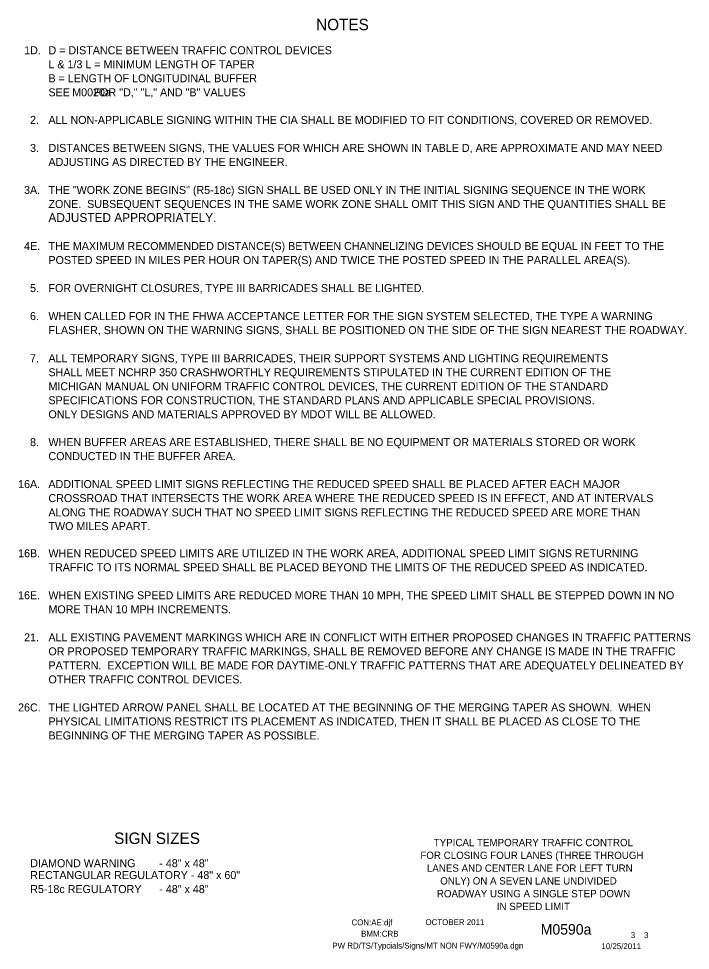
# Model space of a CAD drawing. Extents: x 16730 to 19504, y 5662 to 6979.
# Drawn here: x 18799 to 19504, y 5932 to 6909 of the extents above; entities that cross this region are included whole.
import ezdxf

# ---------------------------------------------------------------- set-up
doc = ezdxf.new("R2010")
doc.units = 0
for name, color, linetype in [('BORDER', 7, 'Continuous'), ('BORDER_SIGNAL_WO', 7, 'Continuous'), ('TYPICAL_TEXT_DIMEN_PR', 7, 'Continuous')]:
    doc.layers.add(name, color=color, linetype=linetype)

msp = doc.modelspace()

# ---------------------------------------------------------------- linework, layer by layer
at = {"layer": 'BORDER'}
msp.add_line((18938.25, 6055), (18938.25, 6055), dxfattribs=at)

# ---------------------------------------------------------------- texts
for s, p in [('TYPICAL TEMPORARY TRAFFIC CONTROL', (19234.94, 6041.12)), ('FOR CLOSING FOUR LANES (THREE THROUGH', (19220.94, 6027.72)), ('LANES AND CENTER LANE FOR LEFT TURN', (19227.78, 6014.31)), ('ONLY) ON A SEVEN LANE UNDIVIDED', (19241.76, 6000.91)), ('ROADWAY USING A SINGLE STEP DOWN', (19238.28, 5987.51)), ('IN SPEED LIMIT', (19301.15, 5974.1))]:
    msp.add_text(s, height=7.6471, dxfattribs=at).set_placement(p)
at = {"layer": 'BORDER_SIGNAL_WO'}
for s, height, p in [('CON:AE:djf', 6.2, (19148.69, 5958.06)), ('    OCTOBER 2011    ', 6.2, (19217.08, 5958.34)), ('BMM:CRB   ', 6.2, (19158.81, 5946.17)), ('    M0590a   ', 11, (19330.86, 5948.38)), (' 3    3 ', 6.2, (19439.45, 5944.7)), ('PW RD/TS/Typcials/Signs/MT NON FWY/M0590a.dgn    ', 6.2, (19128.55, 5933.71)), ('10/25/2011    ', 6.2, (19410.93, 5933.13))]:
    msp.add_text(s, height=height, dxfattribs=at).set_placement(p)
at = {"layer": 'TYPICAL_TEXT_DIMEN_PR'}
for s, height, p in [('NOTES', 12, (19111.55, 6897)), ('1D.', 8.4, (18805.19, 6871.81)), ('D = DISTANCE BETWEEN TRAFFIC CONTROL DEVICES', 8.4, (18830.7, 6871.81)), ('L & 1/3 L = MINIMUM LENGTH OF TAPER', 8.4, (18830.7, 6857.11)), ('B = LENGTH OF LONGITUDINAL BUFFER', 8.4, (18830.7, 6842.41)), ('SEE        FOR "D," "L," AND "B" VALUES', 8.4, (18830.7, 6827.71)), ('M0020a', 8.4, (18855.62, 6827.71)), ('2.', 8.4, (18811.39, 6798.75)), ('ALL NON-APPLICABLE SIGNING WITHIN THE CIA SHALL BE MODIFIED TO FIT CONDITIONS, COVERED OR REMOVED.', 8.4, (18830.7, 6798.75)), ('3.', 8.4, (18811.39, 6769.35)), ('DISTANCES BETWEEN SIGNS, THE VALUES FOR WHICH ARE SHOWN IN TABLE D, ARE APPROXIMATE AND MAY NEED', 8.4, (18830.7, 6769.35)), ('ADJUSTING AS DIRECTED BY THE ENGINEER.', 8.4, (18830.7, 6754.65)), ('THE "WORK ZONE BEGINS" (R5-18c) SIGN SHALL BE USED ONLY IN THE INITIAL SIGNING SEQUENCE IN THE WORK', 8.4, (18830.7, 6725.25)), ('3A.', 8.4, (18805.09, 6725.25)), ('ZONE.  SUBSEQUENT SEQUENCES IN THE SAME WORK ZONE SHALL OMIT THIS SIGN AND THE QUANTITIES SHALL BE', 8.4, (18830.7, 6710.55)), ('ADJUSTED APPROPRIATELY.', 9.3, (18830.7, 6695.85)), ('THE MAXIMUM RECOMMENDED DISTANCE(S) BETWEEN CHANNELIZING DEVICES SHOULD BE EQUAL IN FEET TO THE', 8.4, (18830.7, 6666.45)), ('4E.', 8.4, (18805.13, 6666.45)), ('POSTED SPEED IN MILES PER HOUR ON TAPER(S) AND TWICE THE POSTED SPEED IN THE PARALLEL AREA(S).', 8.4, (18830.7, 6651.75)), ('5.', 8.4, (18811.39, 6622.35)), ('FOR OVERNIGHT CLOSURES, TYPE III BARRICADES SHALL BE LIGHTED.', 8.4, (18830.7, 6622.35)), ('6.', 8.4, (18811.34, 6592.95)), ('WHEN CALLED FOR IN THE FHWA ACCEPTANCE LETTER FOR THE SIGN SYSTEM SELECTED, THE TYPE A WARNING ', 8.4, (18830.7, 6592.95)), ('FLASHER, SHOWN ON THE WARNING SIGNS, SHALL BE POSITIONED ON THE SIDE OF THE SIGN NEAREST THE ROADWAY.', 8.4, (18830.7, 6578.25)), ('7.', 8.4, (18811.34, 6548.76)), ('ALL TEMPORARY SIGNS, TYPE III BARRICADES, THEIR SUPPORT SYSTEMS AND LIGHTING REQUIREMENTS', 8.4, (18830.7, 6548.78)), ('SHALL MEET NCHRP 350 CRASHWORTHLY REQUIREMENTS STIPULATED IN THE CURRENT EDITION OF THE', 8.4, (18830.7, 6534.08)), ('MICHIGAN MANUAL ON UNIFORM TRAFFIC CONTROL DEVICES, THE CURRENT EDITION OF THE STANDARD', 8.4, (18830.7, 6519.38)), ('SPECIFICATIONS FOR CONSTRUCTION, THE STANDARD PLANS AND APPLICABLE SPECIAL PROVISIONS.', 8.4, (18830.7, 6504.68)), ('ONLY DESIGNS AND MATERIALS APPROVED BY MDOT WILL BE ALLOWED.', 8.4, (18830.7, 6489.98)), ('8.', 8.4, (18811.39, 6460.76)), ('WHEN BUFFER AREAS ARE ESTABLISHED, THERE SHALL BE NO EQUIPMENT OR MATERIALS STORED OR WORK     ', 8.4, (18830.7, 6460.76)), ('CONDUCTED IN THE BUFFER AREA.', 8.4, (18830.7, 6446.06)), ('16A.', 8.4, (18798.84, 6416.75)), ('ADDITIONAL SPEED LIMIT SIGNS REFLECTING THE REDUCED SPEED SHALL BE PLACED AFTER EACH MAJOR', 8.4, (18830.7, 6416.75)), ('CROSSROAD THAT INTERSECTS THE WORK AREA WHERE THE REDUCED SPEED IS IN EFFECT, AND AT INTERVALS', 8.4, (18830.7, 6402.05)), ('ALONG THE ROADWAY SUCH THAT NO SPEED LIMIT SIGNS REFLECTING THE REDUCED SPEED ARE MORE THAN', 8.4, (18830.7, 6387.05)), ('TWO MILES APART.', 8.4, (18830.7, 6372.65)), ('16B.', 8.4, (18798.84, 6344.17)), ('WHEN REDUCED SPEED LIMITS ARE UTILIZED IN THE WORK AREA, ADDITIONAL SPEED LIMIT SIGNS RETURNING', 8.4, (18830.7, 6344.23)), ('TRAFFIC TO ITS NORMAL SPEED SHALL BE PLACED BEYOND THE LIMITS OF THE REDUCED SPEED AS INDICATED.', 8.4, (18830.7, 6329.53)), ('16E.', 8.4, (18798.84, 6300.12)), ('WHEN EXISTING SPEED LIMITS ARE REDUCED MORE THAN 10 MPH, THE SPEED LIMIT SHALL BE STEPPED DOWN IN NO', 8.4, (18830.7, 6300.12)), ('MORE THAN 10 MPH INCREMENTS.', 8.4, (18830.7, 6285.42)), ('21.', 8.4, (18805.14, 6255.97)), ('ALL EXISTING PAVEMENT MARKINGS WHICH ARE IN CONFLICT WITH EITHER PROPOSED CHANGES IN TRAFFIC PATTERNS', 8.4, (18830.7, 6255.97)), ('OR PROPOSED TEMPORARY TRAFFIC MARKINGS, SHALL BE REMOVED BEFORE ANY CHANGE IS MADE IN THE TRAFFIC', 8.4, (18830.7, 6241.27)), ('PATTERN.  EXCEPTION WILL BE MADE FOR DAYTIME-ONLY TRAFFIC PATTERNS THAT ARE ADEQUATELY DELINEATED BY', 8.4, (18830.7, 6226.57)), ('OTHER TRAFFIC CONTROL DEVICES.', 8.4, (18830.7, 6211.87)), ('26C.', 8.4, (18798.83, 6182.47)), ('THE LIGHTED ARROW PANEL SHALL BE LOCATED AT THE BEGINNING OF THE MERGING TAPER AS SHOWN.  WHEN', 8.4, (18830.7, 6182.47)), ('PHYSICAL LIMITATIONS RESTRICT ITS PLACEMENT AS INDICATED, THEN IT SHALL BE PLACED AS CLOSE TO THE', 8.4, (18830.7, 6167.77)), ('BEGINNING OF THE MERGING TAPER AS POSSIBLE.', 8.4, (18830.7, 6153.07)), ('SIGN SIZES', 12, (18899.61, 6043.43)), ('DIAMOND WARNING        - 48" x 48"', 8.4, (18811.57, 6019.03)), ('RECTANGULAR REGULATORY - 48" x 60"', 8.4, (18811.57, 6006.63)), ('R5-18c REGULATORY      - 48" x 48"', 8.4, (18811.57, 5991.93))]:
    msp.add_text(s, height=height, dxfattribs=at).set_placement(p)

doc.saveas('drawing.dxf')
